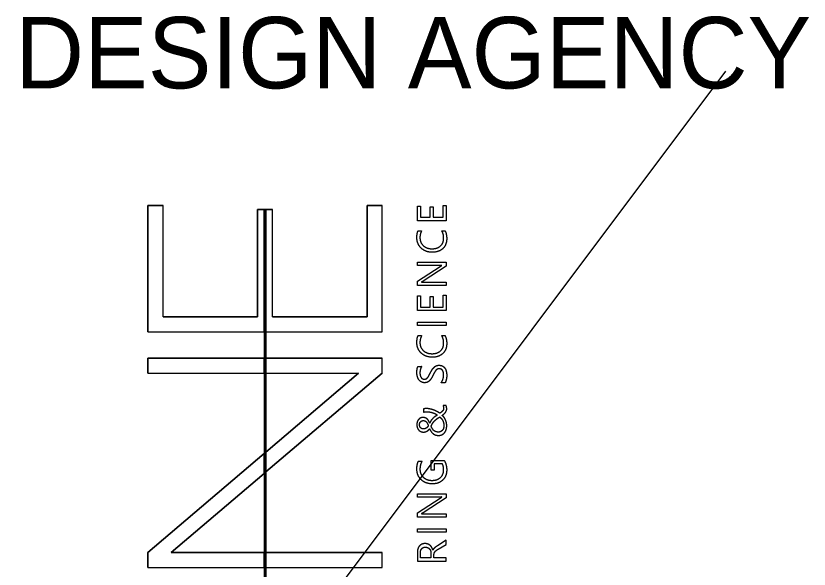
# Model space of a CAD drawing. Extents: x 0 to 63, y -1.2 to 22.
# Drawn here: x 32.051 to 33.162, y 3.677 to 4.451 of the extents above; entities that cross this region are included whole.
import ezdxf

# ---------------------------------------------------------------- set-up
doc = ezdxf.new("R2010")
doc.units = 0
doc.layers.add('SH_Data', color=7, linetype='Continuous')
doc.layers.add('SH_Text', color=7, linetype='Continuous')

msp = doc.modelspace()

# ---------------------------------------------------------------- linework, layer by layer
at = {"layer": 'SH_Data'}
for p, q in [((32.236, 4.1862), (32.2571, 4.1862)), ((32.236, 4.0091), (32.236, 4.1862)), ((32.2571, 4.0302), (32.2571, 4.1862)), ((32.3894, 4.0302), (32.3894, 4.1805)), ((32.3894, 4.1805), (32.3986, 4.1805)), ((32.3986, 4.1805), (32.3986, 3.5525)), ((32.3986, 4.1805), (32.3986, 4.0091)), ((32.3986, 4.1805), (32.4012, 4.1805)), ((32.4012, 4.1805), (32.4012, 3.5525)), ((32.4012, 4.1805), (32.4012, 4.0091)), ((32.4012, 4.1805), (32.4104, 4.1805)), ((32.4104, 4.0302), (32.4104, 4.1805)), ((32.5427, 4.1862), (32.5638, 4.1862)), ((32.5427, 4.0302), (32.5427, 4.1862)), ((32.5638, 4.0091), (32.5638, 4.1862)), ((32.6142, 4.1507), (32.6192, 4.1507)), ((32.6473, 4.1507), (32.6519, 4.1507)), ((32.6476, 4.1022), (32.6476, 4.1023)), ((32.6189, 4.0789), (32.6189, 4.0787)), ((32.2571, 4.0302), (32.3894, 4.0302)), ((32.4104, 4.0302), (32.5427, 4.0302)), ((32.236, 4.0091), (32.3986, 4.0091)), ((32.4012, 4.0091), (32.5638, 4.0091)), ((32.6142, 4.0039), (32.6192, 4.0039)), ((32.6473, 4.0039), (32.6519, 4.0039)), ((32.236, 3.9514), (32.236, 3.9725)), ((32.236, 3.9725), (32.3986, 3.9725)), ((32.3986, 3.9725), (32.3986, 3.9514)), ((32.4012, 3.9725), (32.4012, 3.9514)), ((32.4012, 3.9725), (32.5638, 3.9725)), ((32.5638, 3.9514), (32.5638, 3.9725)), ((32.614, 3.9607), (32.6193, 3.9607)), ((32.236, 3.9514), (32.3986, 3.9514)), ((32.4012, 3.841), (32.531, 3.9514)), ((32.5638, 3.9514), (32.4012, 3.8132)), ((32.4012, 3.9514), (32.531, 3.9514)), ((32.652, 3.9379), (32.6464, 3.9379)), ((32.622, 3.9014), (32.622, 3.8969)), ((32.6535, 3.9059), (32.6492, 3.9059)), ((32.6543, 3.9016), (32.6543, 3.9016)), ((32.6215, 3.885), (32.6215, 3.885)), ((32.6503, 3.8779), (32.6503, 3.8779)), ((32.236, 3.7004), (32.3986, 3.8388)), ((32.3986, 3.8388), (32.3986, 3.811)), ((32.4012, 3.841), (32.4012, 3.8132)), ((32.6147, 3.8284), (32.6199, 3.8284)), ((32.3986, 3.811), (32.2685, 3.7004)), ((32.6476, 3.778), (32.6476, 3.7781)), ((32.6189, 3.7547), (32.6189, 3.7545)), ((32.236, 3.6793), (32.236, 3.7004)), ((32.2685, 3.7004), (32.3986, 3.7004)), ((32.3986, 3.7004), (32.3986, 3.6793)), ((32.4012, 3.7004), (32.4012, 3.6793)), ((32.4012, 3.7004), (32.5638, 3.7004)), ((32.5638, 3.6793), (32.5638, 3.7004)), ((32.635, 3.7038), (32.6349, 3.7038)), ((32.236, 3.6793), (32.3986, 3.6793)), ((32.4012, 3.6793), (32.5638, 3.6793))]:
    msp.add_line(p, q, dxfattribs=at)
for points in [[(32.236, 4.1862), (32.236, 4.0091), (32.3986, 4.0091), (32.3986, 4.1805), (32.3894, 4.1805), (32.3894, 4.0302), (32.2571, 4.0302), (32.2571, 4.1862)], [(32.4104, 4.0302), (32.4104, 4.1805), (32.4012, 4.1805), (32.4012, 4.0091), (32.5638, 4.0091), (32.5638, 4.1862), (32.5427, 4.1862), (32.5427, 4.0302)], [(32.6536, 4.1862), (32.6536, 4.1648), (32.6132, 4.1648), (32.6132, 4.1853), (32.6175, 4.1853), (32.6175, 4.1695), (32.6309, 4.1695), (32.6309, 4.1841), (32.6352, 4.1841), (32.6352, 4.1695), (32.6493, 4.1695), (32.6493, 4.1862)], [(32.6536, 4.0605), (32.6536, 4.0391), (32.6132, 4.0391), (32.6132, 4.0596), (32.6175, 4.0596), (32.6175, 4.0439), (32.6309, 4.0439), (32.6309, 4.0585), (32.6352, 4.0585), (32.6352, 4.0439), (32.6493, 4.0439), (32.6493, 4.0605)], [(32.6536, 4.0226), (32.6536, 4.0179), (32.6132, 4.0179), (32.6132, 4.0226)], [(32.236, 3.9725), (32.236, 3.9514), (32.3986, 3.9514), (32.3986, 3.9725)], [(32.4012, 3.9725), (32.4012, 3.9514), (32.531, 3.9514), (32.4012, 3.841), (32.4012, 3.8132), (32.5638, 3.9514), (32.5638, 3.9725)], [(32.236, 3.7004), (32.236, 3.6793), (32.3986, 3.6793), (32.3986, 3.7004), (32.2685, 3.7004), (32.3986, 3.811), (32.3986, 3.8388)], [(32.6536, 3.7335), (32.6536, 3.7288), (32.6132, 3.7288), (32.6132, 3.7335)], [(32.4012, 3.7004), (32.4012, 3.6793), (32.5638, 3.6793), (32.5638, 3.7004)]]:
    msp.add_lwpolyline(points, close=True, dxfattribs=at)
for points in [[(32.5102, 3.5489), (32.4037, 3.5226), (32.4037, 3.5525), (32.4012, 3.5525), (32.4012, 4.1805), (32.3986, 4.1805), (32.3986, 3.5525), (32.3961, 3.5525), (32.3961, 3.5207), (32.3367, 3.506)], [(32.6417, 4.102), (32.6132, 4.102), (32.6132, 4.1068), (32.6536, 4.1068), (32.6536, 4.101), (32.6214, 4.0801)], [(32.6244, 4.0789), (32.6536, 4.0789), (32.6536, 4.0742), (32.6132, 4.0742), (32.6132, 4.0803), (32.6449, 4.1006)], [(32.6482, 3.8245), (32.6368, 3.8245), (32.6368, 3.8157), (32.6325, 3.8157), (32.6325, 3.8292), (32.6509, 3.8292)], [(32.6417, 3.7778), (32.6132, 3.7778), (32.6132, 3.7826), (32.6536, 3.7826), (32.6536, 3.7768), (32.6214, 3.756)], [(32.6244, 3.7547), (32.6536, 3.7547), (32.6536, 3.75), (32.6132, 3.75), (32.6132, 3.7561), (32.6449, 3.7764)], [(32.6423, 3.705), (32.6536, 3.7117), (32.6536, 3.7174), (32.6415, 3.7098)], [(32.6132, 3.7005), (32.6132, 3.6884), (32.6536, 3.6884), (32.6536, 3.6931), (32.6364, 3.6931), (32.6364, 3.697)], [(32.6321, 3.6996), (32.6321, 3.6931), (32.6175, 3.6931), (32.6175, 3.6996)]]:
    msp.add_lwpolyline(points, dxfattribs=at)
for points in [[(32.6125, 4.1412), (32.6125, 4.1469), (32.6142, 4.1507)], [(32.6192, 4.1507), (32.6168, 4.1464), (32.6168, 4.1411)], [(32.65, 4.1402), (32.65, 4.1463), (32.6473, 4.1507)], [(32.6519, 4.1507), (32.6543, 4.1462), (32.6543, 4.1396)], [(32.6185, 4.1264), (32.6125, 4.1322), (32.6125, 4.1412)], [(32.6168, 4.1411), (32.6168, 4.1342), (32.6215, 4.1298)], [(32.6457, 4.1296), (32.65, 4.1336), (32.65, 4.1402)], [(32.6543, 4.1396), (32.6543, 4.1309), (32.6488, 4.1257)], [(32.6342, 4.1206), (32.6245, 4.1206), (32.6185, 4.1264)], [(32.6215, 4.1298), (32.6261, 4.1255), (32.6339, 4.1255)], [(32.6339, 4.1255), (32.6413, 4.1255), (32.6457, 4.1296)], [(32.6488, 4.1257), (32.6432, 4.1206), (32.6342, 4.1206)], [(32.6476, 4.1023), (32.6459, 4.102), (32.6417, 4.102)], [(32.6449, 4.1006), (32.6469, 4.1018), (32.6476, 4.1022)], [(32.6214, 4.0801), (32.6202, 4.0794), (32.6189, 4.0789)], [(32.6189, 4.0787), (32.6202, 4.0789), (32.6244, 4.0789)], [(32.6125, 3.9943), (32.6125, 4.0001), (32.6142, 4.0039)], [(32.6192, 4.0039), (32.6168, 3.9995), (32.6168, 3.9943)], [(32.65, 3.9933), (32.65, 3.9994), (32.6473, 4.0039)], [(32.6519, 4.0039), (32.6543, 3.9994), (32.6543, 3.9927)], [(32.6185, 3.9795), (32.6125, 3.9854), (32.6125, 3.9943)], [(32.6168, 3.9943), (32.6168, 3.9873), (32.6215, 3.983)], [(32.6457, 3.9827), (32.65, 3.9867), (32.65, 3.9933)], [(32.6543, 3.9927), (32.6543, 3.9841), (32.6488, 3.9789)], [(32.6342, 3.9737), (32.6245, 3.9737), (32.6185, 3.9795)], [(32.6215, 3.983), (32.6261, 3.9786), (32.6339, 3.9786)], [(32.6339, 3.9786), (32.6413, 3.9786), (32.6457, 3.9827)], [(32.6488, 3.9789), (32.6432, 3.9737), (32.6342, 3.9737)], [(32.6125, 3.952), (32.6125, 3.958), (32.614, 3.9607)], [(32.6193, 3.9607), (32.6168, 3.9572), (32.6168, 3.9516)], [(32.6314, 3.9517), (32.6324, 3.9539), (32.6336, 3.9558)], [(32.6336, 3.9558), (32.6348, 3.9578), (32.6362, 3.9592)], [(32.6362, 3.9592), (32.6377, 3.9607), (32.6394, 3.9616)], [(32.6387, 3.9548), (32.6377, 3.9535), (32.6368, 3.9518)], [(32.6409, 3.9568), (32.6397, 3.956), (32.6387, 3.9548)], [(32.6394, 3.9616), (32.6412, 3.9624), (32.6434, 3.9624)], [(32.6438, 3.9575), (32.6421, 3.9575), (32.6409, 3.9568)], [(32.6434, 3.9624), (32.6464, 3.9624), (32.6485, 3.9613)], [(32.6484, 3.9553), (32.6468, 3.9575), (32.6438, 3.9575)], [(32.65, 3.9488), (32.65, 3.9532), (32.6484, 3.9553)], [(32.6485, 3.9613), (32.6506, 3.9601), (32.6519, 3.9581)], [(32.6519, 3.9581), (32.6532, 3.9561), (32.6537, 3.9535)], [(32.6537, 3.9535), (32.6543, 3.9509), (32.6543, 3.9481)], [(32.6132, 3.9469), (32.6125, 3.9494), (32.6125, 3.952)], [(32.6151, 3.9424), (32.6138, 3.9444), (32.6132, 3.9469)], [(32.6168, 3.9516), (32.6168, 3.95), (32.6171, 3.9484)], [(32.6171, 3.9484), (32.6175, 3.9469), (32.6182, 3.9457)], [(32.6182, 3.9457), (32.6189, 3.9445), (32.6201, 3.9437)], [(32.6201, 3.9437), (32.6212, 3.943), (32.6229, 3.943)], [(32.6229, 3.943), (32.6244, 3.943), (32.6256, 3.9435)], [(32.6256, 3.9435), (32.6267, 3.9441), (32.6276, 3.9452)], [(32.6276, 3.9452), (32.6286, 3.9464), (32.6294, 3.948)], [(32.6294, 3.948), (32.6303, 3.9496), (32.6314, 3.9517)], [(32.6327, 3.9441), (32.6316, 3.9422), (32.6303, 3.9409)], [(32.6349, 3.948), (32.6338, 3.9459), (32.6327, 3.9441)], [(32.6368, 3.9518), (32.6359, 3.95), (32.6349, 3.948)], [(32.6479, 3.9402), (32.6486, 3.9416), (32.6491, 3.9431)], [(32.6491, 3.9431), (32.6495, 3.9445), (32.6498, 3.946)], [(32.6498, 3.946), (32.65, 3.9475), (32.65, 3.9488)], [(32.6537, 3.9428), (32.6534, 3.9413), (32.653, 3.94)], [(32.6542, 3.9457), (32.654, 3.9443), (32.6537, 3.9428)], [(32.6543, 3.9481), (32.6543, 3.9471), (32.6542, 3.9457)], [(32.6185, 3.9392), (32.6165, 3.9404), (32.6151, 3.9424)], [(32.6233, 3.938), (32.6206, 3.938), (32.6185, 3.9392)], [(32.6273, 3.9388), (32.6256, 3.938), (32.6233, 3.938)], [(32.6303, 3.9409), (32.6289, 3.9395), (32.6273, 3.9388)], [(32.6464, 3.9379), (32.6473, 3.9389), (32.6479, 3.9402)], [(32.653, 3.94), (32.6525, 3.9387), (32.652, 3.9379)], [(32.6238, 3.9017), (32.623, 3.9016), (32.622, 3.9014)], [(32.6258, 3.9018), (32.6246, 3.9017), (32.6238, 3.9017)], [(32.6309, 3.9012), (32.6283, 3.9018), (32.6258, 3.9018)], [(32.636, 3.8998), (32.6335, 3.9007), (32.6309, 3.9012)], [(32.6406, 3.8977), (32.6384, 3.8989), (32.636, 3.8998)], [(32.6487, 3.8986), (32.648, 3.8978), (32.647, 3.897)], [(32.6497, 3.9003), (32.6493, 3.8994), (32.6487, 3.8986)], [(32.6492, 3.9059), (32.6495, 3.9049), (32.6498, 3.9041)], [(32.65, 3.9024), (32.65, 3.9012), (32.6497, 3.9003)], [(32.6498, 3.9041), (32.65, 3.9032), (32.65, 3.9024)], [(32.6526, 3.8965), (32.6534, 3.8975), (32.6538, 3.8987)], [(32.6541, 3.9037), (32.6539, 3.9049), (32.6535, 3.9059)], [(32.6538, 3.8987), (32.6543, 3.9), (32.6543, 3.9016)], [(32.6543, 3.9016), (32.6543, 3.9026), (32.6541, 3.9037)], [(32.6176, 3.8886), (32.616, 3.8878), (32.6149, 3.8865)], [(32.6211, 3.8893), (32.6191, 3.8893), (32.6176, 3.8886)], [(32.6267, 3.8874), (32.6245, 3.8893), (32.6211, 3.8893)], [(32.622, 3.8969), (32.623, 3.8971), (32.6239, 3.8973)], [(32.6239, 3.8973), (32.6248, 3.8974), (32.6259, 3.8974)], [(32.6259, 3.8974), (32.6301, 3.8974), (32.634, 3.8962)], [(32.6305, 3.8816), (32.629, 3.8854), (32.6267, 3.8874)], [(32.6349, 3.888), (32.6335, 3.8867), (32.6324, 3.8851)], [(32.634, 3.8962), (32.6378, 3.8951), (32.641, 3.8928)], [(32.6378, 3.8905), (32.6362, 3.8894), (32.6349, 3.888)], [(32.6367, 3.8841), (32.6381, 3.8856), (32.64, 3.887)], [(32.641, 3.8928), (32.6393, 3.8917), (32.6378, 3.8905)], [(32.64, 3.887), (32.6419, 3.8885), (32.6446, 3.8902)], [(32.6446, 3.8952), (32.6428, 3.8965), (32.6406, 3.8977)], [(32.647, 3.897), (32.646, 3.8962), (32.6446, 3.8952)], [(32.6446, 3.8902), (32.6457, 3.8892), (32.6468, 3.8879)], [(32.6468, 3.8879), (32.6478, 3.8867), (32.6486, 3.8852)], [(32.648, 3.8924), (32.6495, 3.8935), (32.6506, 3.8944)], [(32.6504, 3.8898), (32.6492, 3.8913), (32.648, 3.8924)], [(32.6524, 3.8865), (32.6515, 3.8883), (32.6504, 3.8898)], [(32.6506, 3.8944), (32.6518, 3.8954), (32.6526, 3.8965)], [(32.6131, 3.8834), (32.6125, 3.8816), (32.6125, 3.8794)], [(32.6125, 3.8794), (32.6125, 3.8771), (32.6131, 3.8752)], [(32.6149, 3.8865), (32.6137, 3.8852), (32.6131, 3.8834)], [(32.6162, 3.8794), (32.6162, 3.8803), (32.6165, 3.8813)], [(32.6177, 3.875), (32.6162, 3.8766), (32.6162, 3.8794)], [(32.6165, 3.8813), (32.6168, 3.8823), (32.6175, 3.8831)], [(32.6175, 3.8831), (32.6181, 3.8839), (32.6191, 3.8844)], [(32.6191, 3.8844), (32.6201, 3.885), (32.6215, 3.885)], [(32.6215, 3.885), (32.624, 3.885), (32.6256, 3.8832)], [(32.6256, 3.8832), (32.6273, 3.8815), (32.6285, 3.8779)], [(32.6274, 3.8761), (32.6267, 3.8753), (32.6258, 3.8746)], [(32.6285, 3.8779), (32.6281, 3.877), (32.6274, 3.8761)], [(32.6324, 3.8851), (32.6313, 3.8835), (32.6305, 3.8816)], [(32.6325, 3.8771), (32.6334, 3.8793), (32.6344, 3.8809)], [(32.6341, 3.8738), (32.6332, 3.8753), (32.6325, 3.8771)], [(32.6344, 3.8809), (32.6354, 3.8826), (32.6367, 3.8841)], [(32.6486, 3.8852), (32.6493, 3.8837), (32.6498, 3.8819)], [(32.6498, 3.8819), (32.6503, 3.8801), (32.6503, 3.8779)], [(32.6503, 3.8779), (32.6503, 3.876), (32.6498, 3.8744)], [(32.6538, 3.8826), (32.6532, 3.8847), (32.6524, 3.8865)], [(32.6535, 3.8723), (32.6543, 3.8749), (32.6543, 3.8779)], [(32.6543, 3.8779), (32.6543, 3.8804), (32.6538, 3.8826)], [(32.6131, 3.8752), (32.6137, 3.8733), (32.6149, 3.8719)], [(32.6149, 3.8719), (32.6161, 3.8705), (32.6178, 3.8697)], [(32.6218, 3.8733), (32.6192, 3.8733), (32.6177, 3.875)], [(32.6178, 3.8697), (32.6195, 3.8689), (32.6218, 3.8689)], [(32.6239, 3.8736), (32.6229, 3.8733), (32.6218, 3.8733)], [(32.6218, 3.8689), (32.6233, 3.8689), (32.6246, 3.8693)], [(32.6258, 3.8746), (32.625, 3.874), (32.6239, 3.8736)], [(32.6246, 3.8693), (32.6259, 3.8697), (32.6269, 3.8704)], [(32.6269, 3.8704), (32.628, 3.871), (32.6288, 3.8719)], [(32.6288, 3.8719), (32.6296, 3.8727), (32.6303, 3.8736)], [(32.6303, 3.8736), (32.6322, 3.8691), (32.6353, 3.8666)], [(32.6361, 3.8712), (32.635, 3.8723), (32.6341, 3.8738)], [(32.6353, 3.8666), (32.6383, 3.8642), (32.6426, 3.8642)], [(32.6389, 3.8695), (32.6373, 3.8701), (32.6361, 3.8712)], [(32.6425, 3.8689), (32.6404, 3.8689), (32.6389, 3.8695)], [(32.6459, 3.8696), (32.6444, 3.8689), (32.6425, 3.8689)], [(32.6426, 3.8642), (32.6455, 3.8642), (32.6476, 3.8652)], [(32.6483, 3.8715), (32.6473, 3.8703), (32.6459, 3.8696)], [(32.6476, 3.8652), (32.6498, 3.8662), (32.6513, 3.868)], [(32.6498, 3.8744), (32.6493, 3.8727), (32.6483, 3.8715)], [(32.6513, 3.868), (32.6528, 3.8698), (32.6535, 3.8723)], [(32.6125, 3.8174), (32.6125, 3.8239), (32.6147, 3.8284)], [(32.6199, 3.8284), (32.6168, 3.8235), (32.6168, 3.8168)], [(32.65, 3.8163), (32.65, 3.821), (32.6482, 3.8245)], [(32.6509, 3.8292), (32.6543, 3.8232), (32.6543, 3.8157)], [(32.6185, 3.8023), (32.6125, 3.8082), (32.6125, 3.8174)], [(32.6168, 3.8168), (32.6168, 3.81), (32.6215, 3.8057)], [(32.6457, 3.8054), (32.65, 3.8094), (32.65, 3.8163)], [(32.6543, 3.8157), (32.6543, 3.8071), (32.6487, 3.8017)], [(32.634, 3.7964), (32.6246, 3.7964), (32.6185, 3.8023)], [(32.6215, 3.8057), (32.6262, 3.8013), (32.6336, 3.8013)], [(32.6336, 3.8013), (32.6413, 3.8013), (32.6457, 3.8054)], [(32.6487, 3.8017), (32.6431, 3.7964), (32.634, 3.7964)], [(32.6476, 3.7781), (32.6459, 3.7778), (32.6417, 3.7778)], [(32.6449, 3.7764), (32.6469, 3.7776), (32.6476, 3.778)], [(32.6214, 3.756), (32.6202, 3.7552), (32.6189, 3.7547)], [(32.6189, 3.7545), (32.6202, 3.7547), (32.6244, 3.7547)], [(32.6159, 3.7093), (32.6145, 3.7076), (32.6139, 3.7054)], [(32.6192, 3.7118), (32.6172, 3.7109), (32.6159, 3.7093)], [(32.624, 3.7128), (32.6213, 3.7128), (32.6192, 3.7118)], [(32.6278, 3.7121), (32.6261, 3.7128), (32.624, 3.7128)], [(32.631, 3.7103), (32.6296, 3.7115), (32.6278, 3.7121)], [(32.6333, 3.7075), (32.6324, 3.7092), (32.631, 3.7103)], [(32.6415, 3.7098), (32.6402, 3.709), (32.6392, 3.7083)], [(32.6139, 3.7054), (32.6132, 3.7031), (32.6132, 3.7005)], [(32.6175, 3.6996), (32.6175, 3.7036), (32.6193, 3.7057)], [(32.6193, 3.7057), (32.6211, 3.7078), (32.6244, 3.7078)], [(32.6244, 3.7078), (32.6262, 3.7078), (32.6276, 3.7072)], [(32.6276, 3.7072), (32.6291, 3.7066), (32.6301, 3.7055)], [(32.6301, 3.7055), (32.6311, 3.7044), (32.6316, 3.7029)], [(32.6316, 3.7029), (32.6321, 3.7013), (32.6321, 3.6996)], [(32.6349, 3.7038), (32.6343, 3.7059), (32.6333, 3.7075)], [(32.636, 3.7056), (32.6354, 3.7048), (32.635, 3.7038)], [(32.6374, 3.707), (32.6366, 3.7063), (32.636, 3.7056)], [(32.6364, 3.697), (32.6364, 3.6984), (32.6368, 3.6994)], [(32.6368, 3.6994), (32.6371, 3.7005), (32.6378, 3.7014)], [(32.6392, 3.7083), (32.6382, 3.7077), (32.6374, 3.707)], [(32.6378, 3.7014), (32.6385, 3.7023), (32.6396, 3.7032)], [(32.6396, 3.7032), (32.6407, 3.7041), (32.6423, 3.705)]]:
    msp.add_open_spline(points, degree=2, dxfattribs=at)
at = {"layer": 'SH_Text'}
msp.add_line((31.8448, 2.7741), (33.0448, 4.3741), dxfattribs=at)

# ---------------------------------------------------------------- texts
at = {"layer": 'SH_Data'}
msp.add_text('DESIGN AGENCY', height=0.1, dxfattribs=at).set_placement((32.05, 4.35))

doc.saveas('drawing.dxf')
